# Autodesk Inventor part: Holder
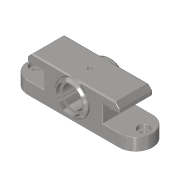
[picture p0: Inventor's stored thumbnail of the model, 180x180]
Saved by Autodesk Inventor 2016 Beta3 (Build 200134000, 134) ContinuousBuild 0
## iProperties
Created: 2016-02
Part Number: Holder
Material: Steel, Cast
Document SubType Name: Modeling
Designer: Vertex
Mass: 1273.57 g
Surface Area: 324.28 cm^2
Volume: 162.238 cm^3
Density: 7.85 g/cm^3
Appearance: Semi-Polished
Title: Apoio
Author: Vertex
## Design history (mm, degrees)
sketch "Sketch1"
  geometry: L1 (75, 45)-(25, 45); L2 (0, 15)-(0, 0); L3 (0, 15)-(40, 15); L4 (40, 35)-(40, 15); L5 (20, 35)-(40, 35); L6 (20, 40)-(20, 35); L7 (20, 40)-(25, 45); L8 (75, 45)-(125, 45); L9 (150, 15)-(150, 0); L10 (150, 15)-(110, 15); L11 (110, 35)-(110, 15); L12 (130, 35)-(110, 35); L13 (130, 40)-(130, 35); L14 (130, 40)-(125, 45); L15 (0, 0)-(150, 0); L16 (75, 50.194)-(75, -5); 5 further points
  constraints: 32 end point, 6 point on line, 2 parallel, 1 horizontal, 1 vertical
  dimensions: "d3" = 40 distance between parallel lines of L2 L4; "d5" = 5 distance of L6.start point (20, 45); "d6" = 5 distance of L1.end point (20, 45) (= d5); "d7" = 150 distance of L9.end L2.end; "d8" = 130 distance of point (140, 15) point (10, 15); "d9" = 20 distance between parallel lines of L12 L10; "d10" = 10 distance from line of L8 L12.start
extrude "Extrusion1" new body sketch "Sketch1" stored distance "d11" = 40; taper "d12" = 0 deg
hole "Hole1" diameter "d15" = 26; stored, may be unused: countersink angle "d19" = 90 deg, drill point angle "d21" = 118 deg; dims "d13" = 75, "d14" = 25, "d16" = 7.5, "d17" = 3.75, "d18" = 2.5, "d20" = 10
hole "Hole2" diameter "d24" = 8; stored, may be unused: countersink angle "d28" = 90 deg, drill point angle "d30" = 118 deg; dims "d22" = 10, "d23" = 20, "d25" = 7.5, "d26" = 13.5, "d27" = 5, "d29" = 10
workplane "Work Plane1"
mirror "Mirror1"
sketch "Sketch2"
  geometry: C1 r 20 at (75, 25); C2 r 16 at (75, 25); 2 further points
  constraints: 2 centre point, 2 coincident
  dimensions: "d34" = 40 diameter of C1; "d40" = 32 diameter of C2
extrude "Extrusion2" join sketch "Sketch2" distance "d35" = 5; taper "d36" = 0 deg
mirror "Mirror2"
chamfer "Chamfer3" distance "d41" = 2.5; stored, may be unused: second distance "d42" = 1.25, angle "d43" = 45 deg
fillet "Fillet1" dims "d65" = 2
fillet "Fillet2" dims "d45" = 1
fillet "Fillet3"
fillet "Fillet4"
hole "Hole3" diameter "d48" = 3; stored, may be unused: countersink angle "d52" = 90 deg, drill point angle "d54" = 118 deg; dims "d46" = 55, "d47" = 20, "d49" = 7.5, "d50" = 5, "d51" = 6, "d53" = 10
fillet "Fillet5" dims "d55" = 0.5
hole "Hole4" diameter "d58" = 4.92; stored, may be unused: countersink angle "d62" = 90 deg, drill point angle "d64" = 118 deg; dims "d56" = 10, "d57" = 10, "d59" = 12, "d60" = 3.75, "d61" = 2.5, "d63" = 17.1
mirror "Mirror4"
mirror "Mirror5"
fillet "Fillet6" dims "d66" = 0.5
body "Solid1"
